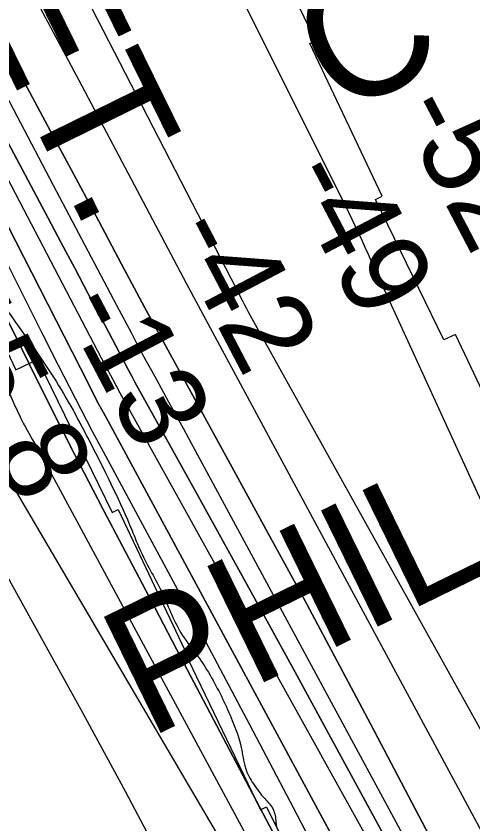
# Model space of a CAD drawing. Extents: x 3355724 to 3393621, y 594744 to 620174.
# Drawn here: x 3383904 to 3384258, y 604441 to 605066 of the extents above; entities that cross this region are included whole.
import ezdxf

# ---------------------------------------------------------------- set-up
doc = ezdxf.new("R2010")
doc.units = 0
for name, color, linetype in [('V-CHAN-NAID', 7, 'Continuous'), ('V-RIVR-EDGE', 7, 'Continuous'), ('V-RIVR-RANG', 7, 'Continuous'), ('V-RRAP-RVMT', 7, 'Continuous'), ('V-RRAP-RVMT-IDEN', 7, 'Continuous'), ('V-TOPO-DPTH', 7, 'Continuous'), ('V-TOPO-MAJR', 7, 'Continuous'), ('V-TOPO-MINR', 7, 'Continuous'), ('V-TOPO-WATR', 7, 'Continuous')]:
    doc.layers.add(name, color=color, linetype=linetype)

msp = doc.modelspace()

# ---------------------------------------------------------------- linework, layer by layer
at = {"layer": 'V-RIVR-EDGE'}
msp.add_spline([(3382685.21, 606951.82), (3382699.41, 606928.39), (3382711.81, 606916.3), (3382716.9, 606906.05), (3382724.91, 606891.77), (3382727.45, 606882.99), (3382735.47, 606874.56), (3382743.12, 606862.48), (3382749.66, 606847.84), (3382757.66, 606833.2), (3382769.68, 606814.16), (3382782.05, 606791.1), (3382790.05, 606772.81), (3382795.49, 606757.44), (3382803.86, 606738.78), (3382815.86, 606716.08), (3382832.97, 606684.6), (3382843.14, 606660.09), (3382859.52, 606629.71), (3382875.17, 606604.81), (3382892.66, 606579.18), (3382909.77, 606553.18), (3382929.07, 606522.43), (3382946.92, 606497.16), (3382961.85, 606475.92), (3382973.16, 606466.75), (3382978.63, 606458.7), (3382989.19, 606442.59), (3382998.29, 606426.48), (3383008.12, 606410.74), (3383014.67, 606399.39), (3383025.61, 606390.23), (3383035.45, 606378.87), (3383042.38, 606369.71), (3383049.66, 606356.54), (3383077.35, 606319.55), (3383102.48, 606284.03), (3383117.05, 606263.15), (3383116.67, 606258.04), (3383121.77, 606250.71), (3383131.61, 606238.99), (3383143.64, 606222.15), (3383154.19, 606202.75), (3383171.3, 606174.92), (3383191.32, 606140.51), (3383212.06, 606099.52), (3383234.24, 606053.04), (3383253.52, 606014.97), (3383268.81, 605988.25), (3383282.64, 605965.55), (3383296.11, 605942.49), (3383311.03, 605917.6), (3383331.43, 605885.38), (3383347.45, 605861.21), (3383359.46, 605839.98), (3383382.76, 605801.54), (3383403.87, 605764.93), (3383419.51, 605733.82), (3383436.64, 605710.75), (3383464.33, 605675.59), (3383488.38, 605644.46), (3383503.69, 605625.05), (3383518.63, 605606.37), (3383529.55, 605590.26), (3383543.77, 605575.6), (3383545.23, 605570.84), (3383546.67, 605564.62), (3383550.31, 605557.3), (3383561.99, 605549.6), (3383575.12, 605539.33), (3383595.9, 605513.69), (3383606.83, 605500.87), (3383607.91, 605493.92), (3383610.43, 605479.66), (3383611.87, 605471.25), (3383616.97, 605461), (3383626.05, 605438.68), (3383628.92, 605416.37), (3383634.35, 605396.99), (3383636.16, 605387.48), (3383637.95, 605374.31), (3383643.05, 605364.07), (3383654.34, 605347.59), (3383664.16, 605328.56), (3383678.7, 605295.99), (3383684.48, 605268.55), (3383701.54, 605220.26), (3383711.72, 605194.65), (3383714.97, 605180.02), (3383724.03, 605149.29), (3383729.84, 605134.29), (3383736.02, 605118.55), (3383753.85, 605084.88), (3383770.61, 605064.73), (3383787.39, 605048.97), (3383790.65, 605036.53), (3383801.19, 605013.11), (3383814.64, 604980.55), (3383827.35, 604948.71), (3383833.53, 604932.98), (3383843.72, 604917.23), (3383863.03, 604890.5), (3383884.52, 604857.18), (3383935.15, 604783.58), (3383963.9, 604731.6), (3383993.72, 604668.66), (3384000.98, 604651.46), (3384017.36, 604619.61), (3384032.99, 604587.04), (3384044.65, 604571.29), (3384055.58, 604554.09), (3384071.58, 604521.15), (3384078.47, 604500.29), (3384081.72, 604484.57), (3384087.91, 604472.12), (3384096.65, 604460.77), (3384103.21, 604452.35), (3384105.38, 604442.47), (3384107.19, 604435.89), (3384108.65, 604434.42), (3384114.86, 604433.67), (3384119.61, 604430.74), (3384126.53, 604421.95), (3384146.92, 604390.46), (3384166.94, 604355.68), (3384183.33, 604328.23), (3384207.01, 604298.92), (3384223.4, 604274.03), (3384250.33, 604225.34), (3384273.98, 604179.96), (3384293.99, 604141.52), (3384308.54, 604112.61), (3384320.91, 604089.55), (3384332.21, 604075.63), (3384335.85, 604069.04), (3384345.31, 604053.3), (3384348.96, 604047.81), (3384362.08, 604034.98), (3384372.29, 604022.89), (3384383.95, 604005.68), (3384390.13, 603992.87), (3384406.16, 603972.36), (3384417.09, 603955.15), (3384430.56, 603933.92), (3384440.75, 603916.71), (3384450.2, 603895.85), (3384454.18, 603879.03), (3384458.53, 603863.66), (3384464.33, 603844.64), (3384471.6, 603825.25), (3384474.86, 603815.01), (3384473.74, 603806.6), (3384477.73, 603791.24), (3384479.17, 603782.1), (3384477.68, 603771.13), (3384476.19, 603762), (3384476.16, 603748.84), (3384481.96, 603727.62), (3384486.67, 603712.26), (3384487.01, 603701.29), (3384486.95, 603678.63), (3384496.34, 603629.99), (3384507.57, 603590.84), (3384519.55, 603555.72), (3384533.36, 603523.52), (3384552.63, 603483.63), (3384569.02, 603455.8), (3384585.77, 603432.73), (3384604.35, 603404.54), (3384620.73, 603379.64), (3384633.81, 603347.08), (3384649.05, 603299.88), (3384654.82, 603268.07), (3384673.29, 603196.37), (3384684.48, 603140.78), (3384695.35, 603099.81), (3384709.16, 603067.61), (3384721.89, 603042.36), (3384733.52, 603015.64), (3384746.6, 602984.9), (3384754.96, 602962.22), (3384756.77, 602956), (3384760.42, 602955.99), (3384764.43, 602951.23), (3384767.66, 602926.73), (3384780.31, 602867.11), (3384791.19, 602833.82), (3384810.8, 602780.4), (3384832.95, 602721.86), (3384845.31, 602691.49), (3384855.14, 602674.65), (3384859.48, 602657.82), (3384867.48, 602641.72), (3384876.95, 602624.52), (3384884.56, 602600.74), (3384894, 602572.2), (3384900.51, 602546.96), (3384906.68, 602528.3), (3384922.67, 602491.34), (3384928.84, 602472.32), (3384931.72, 602454.03), (3384931.31, 602436.86), (3384923.24, 602425.18), (3384917.01, 602416.05), (3384910.77, 602406.93), (3384908.17, 602392.32), (3384903.03, 602383.19), (3384897.53, 602375.89), (3384886.53, 602362.03), (3384870.35, 602324.05), (3384866.3, 602310.9), (3384859.67, 602289.35), (3384857.45, 602280.22), (3384853.41, 602271.82), (3384850.08, 602256.47), (3384849.29, 602231.99), (3384850.71, 602216.63), (3384853.24, 602202.37), (3384853.6, 602202.37), (3384862.01, 602201.25), (3384874.06, 602196.47), (3384877.35, 602195.36), (3384877.34, 602192.44), (3384871.47, 602184.04), (3384871.09, 602180.39), (3384872.91, 602176.73), (3384876.19, 602170.87), (3384874.71, 602165.03), (3384869.57, 602153.71), (3384865.53, 602149.33), (3384862.96, 602143.12), (3384862.95, 602137.64), (3384862.94, 602133.25), (3384868.04, 602129.59), (3384875.7, 602122.99), (3384878.97, 602114.94), (3384881.88, 602107.25), (3384886.98, 602100.66), (3384894.28, 602096.99), (3384896.47, 602092.23), (3384897.16, 602079.43), (3384899.7, 602068.09), (3384904.78, 602054.92), (3384914.25, 602039.55), (3384933.2, 602016.83), (3384944.85, 601998.16), (3384955.39, 601973.28), (3384961.88, 601937.81), (3384969.47, 601901.96), (3384976.33, 601868.68), (3384986.49, 601837.58), (3384990.84, 601821.49), (3384996.23, 601784.56), (3385007.4, 601717.27), (3385010.62, 601690.57), (3385019.64, 601642.3), (3385024.34, 601622.91), (3385033.39, 601587.07), (3385047.89, 601537.32), (3385059.82, 601482.82), (3385064.15, 601458.68), (3385063.72, 601433.83), (3385064.77, 601415.91), (3385066.9, 601389.22), (3385067.94, 601365.09), (3385069.01, 601353.39), (3385072.63, 601339.86), (3385083.54, 601316.8), (3385087.91, 601310.58), (3385095.57, 601305.08), (3385098.12, 601299.59), (3385101.76, 601293.73), (3385102.48, 601288.97), (3385102.47, 601285.68), (3385105.76, 601284.58), (3385109.77, 601282.38), (3385109.77, 601280.91), (3385112.69, 601280.54), (3385119.64, 601280.52), (3385121.82, 601278.33), (3385122.16, 601265.16), (3385118.12, 601257.13), (3385117.74, 601251.29), (3385118.07, 601238.12), (3385119.82, 601205.59), (3385117.98, 601200.84), (3385117.59, 601193.89), (3385120.87, 601189.13), (3385123.07, 601189.13), (3385128.55, 601189.11), (3385132.2, 601189.11), (3385142.79, 601181.77), (3385148.98, 601172.98), (3385150.77, 601159.45), (3385150.36, 601141.54), (3385148.53, 601137.52), (3385144.86, 601132.78), (3385144.11, 601125.84), (3385146.29, 601119.98), (3385150.3, 601115.59), (3385159.79, 601111.18), (3385160.15, 601107.15), (3385154.66, 601103.88), (3385152.82, 601099.13), (3385152.8, 601092.92), (3385153.51, 601084.87), (3385156.79, 601080.11), (3385159.35, 601079.37), (3385173.25, 601082.26), (3385173.24, 601080.8), (3385172.83, 601061.43), (3385176.06, 601037.66), (3385178.96, 601025.59), (3385186.95, 601006.93), (3385193.5, 600994.85), (3385202.97, 600979.84), (3385216.45, 600962.26), (3385223.73, 600947.98), (3385225.88, 600931.16), (3385225.81, 600905.57), (3385225.42, 600892.05), (3385233.05, 600875.58), (3385237.39, 600855.47), (3385241.34, 600826.58), (3385242.36, 600796.6), (3385245.51, 600741.39), (3385245.8, 600708.86), (3385249.65, 600639.4), (3385250.27, 600596.62), (3385259.56, 600509.6), (3385266.36, 600451.1), (3385277.49, 600369.19), (3385281.77, 600323.48), (3385282.73, 600271.57), (3385283.38, 600237.21), (3385284.31, 600195.07)], degree=3, dxfattribs=at)
at = {"layer": 'V-RRAP-RVMT'}
for points in [[(3384606.57, 604133.4), (3384592.72, 604127.44), (3384536.24, 604243.7), (3384531.59, 604241.42), (3384476.66, 604357.61), (3384462.89, 604351.07), (3384408.58, 604461.75), (3384408.13, 604461.53), (3384350.96, 604576.31), (3384352.1, 604576.88), (3384296.87, 604691.47), (3384303.67, 604694.72), (3384244.39, 604819.89), (3384235.3, 604815.58), (3384182.31, 604924.24), (3384187.61, 604926.78), (3384131.61, 605044.91), (3384135.86, 605046.96), (3384076.9, 605170.6)], [(3383709.39, 605144.82), (3383766.08, 605016.21), (3383772.54, 605019.07), (3383829.08, 604900.66), (3383848.27, 604909.75), (3383903.97, 604792.35), (3383920.88, 604800.35), (3383978.59, 604682.23), (3383983.26, 604684.41), (3384034.8, 604575.63), (3384034.01, 604575.28), (3384093.35, 604452.16), (3384097.91, 604454.35), (3384155.69, 604338.36), (3384170.65, 604345.78), (3384228.55, 604227.76), (3384243.11, 604234.88), (3384299.46, 604115.89), (3384304.43, 604118.22), (3384360.55, 604002.69), (3384372.36, 604008.26)]]:
    msp.add_lwpolyline(points, dxfattribs=at)
at = {"layer": 'V-TOPO-DPTH'}
for points in [[(3383668.19, 605466.14), (3383914.76, 605007.08), (3383932.57, 604973.88), (3383950.37, 604940.68), (3383968.13, 604907.47), (3383985.89, 604874.24), (3384003.69, 604841.05), (3384021.59, 604807.9), (3384039.64, 604774.83), (3384057.77, 604741.82), (3384074.37, 604711.75), (3384100.72, 604663.66), (3384126.89, 604615.46), (3384152.76, 604567.1), (3384178.43, 604518.65), (3384306.82, 604274.55)], [(3384306.82, 604274.55), (3384178.43, 604518.65), (3384152.76, 604567.1), (3384126.89, 604615.46), (3384100.72, 604663.66), (3384074.37, 604711.75), (3384057.77, 604741.82), (3384039.64, 604774.83), (3384021.59, 604807.9), (3384003.69, 604841.05), (3383985.89, 604874.24), (3383968.13, 604907.47), (3383950.37, 604940.68), (3383932.57, 604973.88), (3383914.76, 605007.08), (3383668.19, 605466.14)], [(3384295.03, 604237.88), (3384147.6, 604508.4), (3384121.71, 604555.77), (3384095.76, 604603.11), (3384069.71, 604650.4), (3384043.58, 604697.64), (3383996.24, 604783.06), (3383993.75, 604787.58), (3383991.29, 604792.1), (3383988.85, 604796.64), (3383986.44, 604801.2), (3383970.45, 604831.56), (3383960.05, 604851.29), (3383949.62, 604871.02), (3383939.18, 604890.73), (3383928.71, 604910.43), (3383673.17, 605390.97)], [(3384295.03, 604237.88), (3384147.6, 604508.4), (3384121.71, 604555.77), (3384095.76, 604603.11), (3384069.71, 604650.4), (3384043.58, 604697.64), (3383996.24, 604783.06), (3383993.75, 604787.58), (3383991.29, 604792.1), (3383988.85, 604796.64), (3383986.44, 604801.2), (3383970.45, 604831.56), (3383960.05, 604851.29), (3383949.62, 604871.02), (3383939.18, 604890.73), (3383928.71, 604910.43), (3383673.17, 605390.97)], [(3385273.91, 601933.38), (3385091.12, 602534.32), (3385085.56, 602558.46), (3384932.84, 603149.03), (3384930.13, 603156.62), (3384927.08, 603164.08), (3384644.54, 603627.69), (3384640.89, 603635.11), (3384637.36, 603642.57), (3384634, 603650.12), (3384412.02, 604247.82), (3384084.45, 604836.63), (3384082.76, 604839.78), (3384081.1, 604842.94), (3384079.45, 604846.11), (3383807.5, 605373.31)], [(3385273.91, 601933.38), (3385091.12, 602534.32), (3385085.56, 602558.46), (3384932.84, 603149.03), (3384930.13, 603156.62), (3384927.08, 603164.08), (3384644.54, 603627.69), (3384640.89, 603635.11), (3384637.36, 603642.57), (3384634, 603650.12), (3384412.02, 604247.82), (3384084.45, 604836.63), (3384082.76, 604839.78), (3384081.1, 604842.94), (3384079.45, 604846.11), (3383807.5, 605373.31)], [(3383778.01, 605138.06), (3383960.19, 604781.72), (3383966.96, 604768.08), (3383973.75, 604756.15), (3384183.09, 604368.24), (3384259.37, 604230.97), (3384273.77, 604200.28), (3384280.54, 604184.09), (3384313.54, 604101.42), (3384345.72, 604028.12), (3384436.27, 603808.23), (3384514.1, 603603.7), (3384523.42, 603584.1), (3384529.34, 603568.76), (3384540.32, 603534.67), (3384693.42, 603129.02)], [(3383778.01, 605138.06), (3383960.19, 604781.72), (3383966.96, 604768.08), (3383973.75, 604756.15), (3384183.09, 604368.24), (3384259.37, 604230.97), (3384273.77, 604200.28), (3384280.54, 604184.09), (3384313.54, 604101.42), (3384345.72, 604028.12), (3384436.27, 603808.23), (3384514.1, 603603.7), (3384523.42, 603584.1), (3384529.34, 603568.76), (3384540.32, 603534.67), (3384693.42, 603129.02)], [(3384215.41, 604221.28), (3384051.95, 604531.63), (3384031.85, 604569.84), (3384011.77, 604608.05), (3383991.72, 604646.28), (3383971.69, 604684.53), (3383967.58, 604692.37), (3383949.78, 604726.78), (3383932.18, 604761.29), (3383914.9, 604795.97), (3383897.83, 604830.75), (3383753.75, 605127.67)], [(3383910.99, 605094.98), (3383952.69, 605016.53), (3384035.8, 604859.63), (3384045.04, 604842.28), (3384054.34, 604824.97), (3384362.67, 604252.86), (3384498.18, 603910.2), (3384621.81, 603612.01), (3384631.37, 603592.21), (3384681.63, 603490.91), (3384711.18, 603431.98), (3384741.06, 603373.21), (3384771.44, 603314.7), (3384802.15, 603256.37), (3384841.8, 603181.8), (3384852.51, 603160.69), (3384862.67, 603139.32), (3385058.09, 602515.94), (3385059.63, 602509.42), (3385061.1, 602502.88), (3385062.44, 602496.32), (3385063.71, 602489.74), (3385226.79, 601941.02)], [(3383910.99, 605094.98), (3383952.69, 605016.53), (3384035.8, 604859.63), (3384045.04, 604842.28), (3384054.34, 604824.97), (3384362.67, 604252.86), (3384498.18, 603910.2), (3384621.81, 603612.01), (3384631.37, 603592.21), (3384681.63, 603490.91), (3384711.18, 603431.98), (3384741.06, 603373.21), (3384771.44, 603314.7), (3384802.15, 603256.37), (3384841.8, 603181.8), (3384852.51, 603160.69), (3384862.67, 603139.32), (3385058.09, 602515.94), (3385059.63, 602509.42), (3385061.1, 602502.88), (3385062.44, 602496.32), (3385063.71, 602489.74), (3385226.79, 601941.02)]]:
    msp.add_lwpolyline(points, dxfattribs=at)
at = {"layer": 'V-TOPO-MAJR'}
for points in [[(3383841.84, 605552.4), (3384158.83, 604919.76), (3384161.48, 604914.42), (3384164.09, 604909.06), (3384166.67, 604903.67), (3384169.21, 604898.27), (3384171.72, 604892.86), (3384174.22, 604887.45), (3384176.71, 604882.02), (3384179.18, 604876.6), (3384459.27, 604265.48), (3384472.62, 604235.46), (3384609.18, 603924.52), (3384627.18, 603883.23), (3384645.04, 603841.88), (3384662.67, 603800.43), (3384680.16, 603758.92), (3384702.62, 603705.18), (3384709.01, 603690.61), (3384715.73, 603676.2), (3384722.94, 603662.03), (3384945.04, 603216.73)], [(3383665.35, 605084.41), (3383818.04, 604780.85), (3383833.99, 604749.65), (3383850.2, 604718.58), (3383866.8, 604687.72), (3383883.66, 604657.01), (3383919.52, 604592.67), (3383954.22, 604529.73), (3383988.54, 604466.59), (3384022.28, 604403.14)]]:
    msp.add_lwpolyline(points, dxfattribs=at)
at = {"layer": 'V-TOPO-MINR'}
for points in [[(3383668.19, 605466.14), (3383914.76, 605007.08), (3383932.57, 604973.88), (3383950.37, 604940.68), (3383968.13, 604907.47), (3383985.89, 604874.24), (3384003.69, 604841.05), (3384021.59, 604807.9), (3384039.64, 604774.83), (3384057.77, 604741.82), (3384074.37, 604711.75), (3384100.72, 604663.66), (3384126.89, 604615.46), (3384152.76, 604567.1), (3384178.43, 604518.65), (3384306.82, 604274.55)], [(3383653.68, 605397.11), (3383834.44, 605059.34), (3383858.71, 605013.83), (3383882.88, 604968.26), (3383906.91, 604922.62), (3383930.85, 604876.93), (3383967.21, 604807.27), (3383972.94, 604796.4), (3383978.72, 604785.56), (3383984.59, 604774.76), (3383990.51, 604763.99), (3384190.61, 604403.58)], [(3383591.95, 605396.15), (3383890.96, 604721.26), (3383899.16, 604706.98), (3384063.56, 604426.94), (3384088, 604384.91), (3384112.2, 604342.75), (3384136.05, 604300.39), (3384159.66, 604257.9), (3384202.35, 604180.31), (3384204.4, 604176.49), (3384206.4, 604172.64), (3384208.33, 604168.76), (3384210.2, 604164.85), (3384219.98, 604143.96), (3384226.63, 604129.56), (3384233.21, 604115.11), (3384239.64, 604100.61), (3384246, 604086.07), (3384468.5, 603570.25), (3384608.71, 603164.43)], [(3383673.17, 605390.97), (3383928.71, 604910.43), (3383939.18, 604890.73), (3383949.62, 604871.02), (3383960.05, 604851.29), (3383970.45, 604831.56), (3383986.44, 604801.2), (3383988.85, 604796.64), (3383991.29, 604792.1), (3383993.75, 604787.58), (3383996.24, 604783.06), (3384043.58, 604697.64), (3384069.71, 604650.4), (3384095.76, 604603.11), (3384121.71, 604555.77), (3384147.6, 604508.4), (3384295.03, 604237.88)], [(3385273.91, 601933.38), (3385091.12, 602534.32), (3385085.56, 602558.46), (3384932.84, 603149.03), (3384930.13, 603156.62), (3384927.08, 603164.08), (3384644.54, 603627.69), (3384640.89, 603635.11), (3384637.36, 603642.57), (3384634, 603650.12), (3384412.02, 604247.82), (3384084.45, 604836.63), (3384082.76, 604839.78), (3384081.1, 604842.94), (3384079.45, 604846.11), (3383807.5, 605373.31)], [(3383677.38, 605250.12), (3383886.59, 604801.47), (3383889.8, 604794.53), (3383892.99, 604787.59), (3383896.14, 604780.63), (3383899.27, 604773.66), (3383903.28, 604764.69), (3383904.41, 604762.2), (3383905.56, 604759.73), (3383906.75, 604757.28), (3383907.96, 604754.83), (3383909.76, 604751.25), (3383910.43, 604749.97), (3383910.77, 604749.33), (3383911.13, 604748.7), (3383916.95, 604738.35), (3383920.2, 604732.54), (3383923.43, 604726.71), (3383926.63, 604720.87), (3383929.81, 604715.02), (3384208.2, 604198.98)], [(3383753.75, 605127.67), (3383897.83, 604830.75), (3383914.9, 604795.97), (3383932.18, 604761.29), (3383949.78, 604726.78), (3383967.58, 604692.37), (3383971.69, 604684.53), (3383991.72, 604646.28), (3384011.77, 604608.05), (3384031.85, 604569.84), (3384051.95, 604531.63), (3384215.41, 604221.28)], [(3383847.95, 605096.16), (3383876.34, 605042.57), (3383904.69, 604988.95), (3383932.99, 604935.31), (3383981.94, 604842.45), (3383985.75, 604835.23), (3383989.57, 604828.02), (3383993.41, 604820.82), (3383997.25, 604813.62), (3384001.11, 604806.43), (3384004.99, 604799.25), (3384008.91, 604792.08), (3384012.84, 604784.93), (3384016.53, 604778.26), (3384022.3, 604767.77), (3384028.06, 604757.27), (3384033.79, 604746.76), (3384039.5, 604736.24), (3384300.16, 604254.31)], [(3383910.99, 605094.98), (3383952.69, 605016.53), (3384035.8, 604859.63), (3384045.04, 604842.28), (3384054.34, 604824.97), (3384362.67, 604252.86), (3384498.18, 603910.2), (3384621.81, 603612.01), (3384631.37, 603592.21), (3384681.63, 603490.91), (3384711.18, 603431.98), (3384741.06, 603373.21), (3384771.44, 603314.7), (3384802.15, 603256.37), (3384841.8, 603181.8), (3384852.51, 603160.69), (3384862.67, 603139.32), (3385058.09, 602515.94), (3385059.63, 602509.42), (3385061.1, 602502.88), (3385062.44, 602496.32), (3385063.71, 602489.74), (3385226.79, 601941.02)], [(3383797.15, 605073.71), (3383834.44, 605000.14), (3383923.8, 604821.63), (3383936.76, 604796.04), (3383949.87, 604770.52), (3383963.2, 604745.12), (3383976.68, 604719.79), (3384050.71, 604582.2), (3384084.88, 604518.17), (3384118.78, 604453.99), (3384152.25, 604389.59)]]:
    msp.add_lwpolyline(points, dxfattribs=at)
at = {"layer": 'V-TOPO-WATR'}
msp.add_lwpolyline([(3384693.42, 603129.02), (3384540.32, 603534.67), (3384529.34, 603568.76), (3384523.42, 603584.1), (3384514.1, 603603.7), (3384436.27, 603808.23), (3384345.72, 604028.12), (3384313.54, 604101.42), (3384280.54, 604184.09), (3384273.77, 604200.28), (3384259.37, 604230.97), (3384183.09, 604368.24), (3383973.75, 604756.15), (3383966.96, 604768.08), (3383960.19, 604781.72), (3383778.01, 605138.06)], dxfattribs=at)

# ---------------------------------------------------------------- texts
at = {"layer": 'V-CHAN-NAID'}
for s, rotation, p in [('PHILADELPHIA POINT RANGE C REAR', 26.07767, (3384006.27, 604506.72)), (' C FRONT (182.5)', 26.92203, (3384120.5, 604970.51))]:
    msp.add_text(s, height=100, rotation=rotation, dxfattribs=at).set_placement(p)
at = {"layer": 'V-RIVR-RANG'}
for s, rotation, p in [('-52', 297.66853, (3384198.16, 604993.53)), ('-49', 297.66853, (3384111.81, 604942.87)), ('-42', 297.66853, (3384021.79, 604899.22)), ('15.8', 297.38833, (3383827.35, 604840.61)), ('-13', 297.66853, (3383939.23, 604841.33))]:
    msp.add_text(s, height=67, rotation=rotation, dxfattribs=at).set_placement(p)
at = {"layer": 'V-RRAP-RVMT-IDEN'}
msp.add_text('REVET.', height=100, rotation=296.18726, dxfattribs=at).set_placement((3383746.77, 605330.26))

doc.saveas('drawing.dxf')
